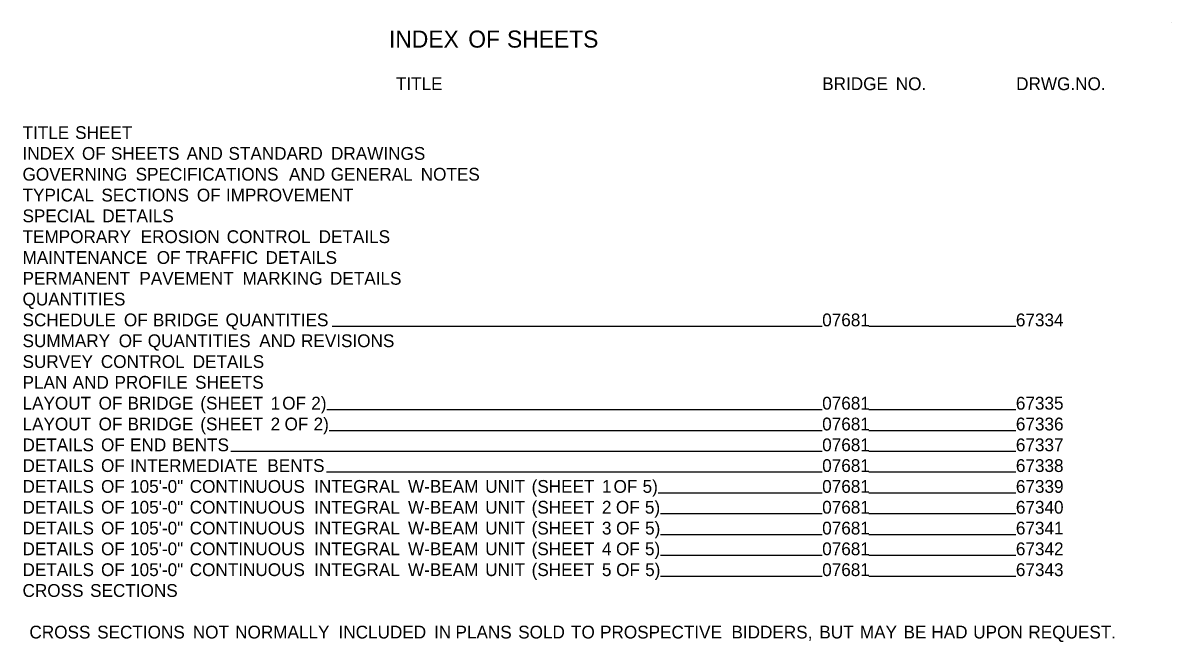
# Model space of a CAD drawing. Extents: x 1334719.7 to 1334768.4, y 402732.4 to 402752.
# Drawn here: x 1334740.16 to 1334753.59, y 402740.62 to 402747.87 of the extents above; entities that cross this region are included whole.
import ezdxf

# ---------------------------------------------------------------- set-up
doc = ezdxf.new("R2010")
doc.units = 0
doc.layers.add('Default', color=7, linetype='Continuous')

msp = doc.modelspace()

# ---------------------------------------------------------------- linework, layer by layer
at = {"layer": 'Default'}
for p, q in [((1334753.594, 402747.87), (1334753.594, 402747.87)), ((1334743.777, 402744.317), (1334749.511, 402744.317)), ((1334750.055, 402744.317), (1334751.778, 402744.317)), ((1334743.711, 402743.342), (1334749.511, 402743.342)), ((1334750.055, 402743.342), (1334751.778, 402743.342)), ((1334743.739, 402743.098), (1334749.511, 402743.098)), ((1334750.055, 402743.098), (1334751.778, 402743.098)), ((1334742.589, 402742.854), (1334749.511, 402742.854)), ((1334750.055, 402742.854), (1334751.778, 402742.854)), ((1334743.707, 402742.611), (1334749.511, 402742.611)), ((1334750.055, 402742.611), (1334751.778, 402742.611)), ((1334747.59, 402742.367), (1334749.511, 402742.367)), ((1334750.055, 402742.367), (1334751.778, 402742.367)), ((1334747.617, 402742.123), (1334749.511, 402742.123)), ((1334750.055, 402742.123), (1334751.778, 402742.123)), ((1334747.619, 402741.879), (1334749.511, 402741.879)), ((1334750.055, 402741.879), (1334751.778, 402741.879)), ((1334747.618, 402741.636), (1334749.511, 402741.636)), ((1334750.055, 402741.636), (1334751.778, 402741.636)), ((1334747.62, 402741.392), (1334749.511, 402741.392)), ((1334750.055, 402741.392), (1334751.778, 402741.392))]:
    msp.add_line(p, q, dxfattribs=at)

# ---------------------------------------------------------------- texts
for s, height, p in [('INDEX', 0.2, (1334744.44, 402747.581)), (' OF', 0.2, (1334745.294, 402747.581)), (' SHEETS', 0.2, (1334745.747, 402747.581)), ('TITLE', 0.15, (1334744.521, 402747.083)), ('BRIDGE', 0.15, (1334749.511, 402747.083)), (' NO.', 0.15, (1334750.316, 402747.083)), ('DRWG.NO.', 0.15, (1334751.781, 402747.083)), ('TITLE', 0.15, (1334740.151, 402746.511)), (' SHEET', 0.15, (1334740.711, 402746.511)), ('INDEX', 0.15, (1334740.151, 402746.267)), (' OF', 0.15, (1334740.791, 402746.267)), (' SHEETS', 0.15, (1334741.13, 402746.267)), (' AND', 0.15, (1334742.016, 402746.267)), (' STANDARD', 0.15, (1334742.506, 402746.267)), (' DRAWINGS', 0.15, (1334743.706, 402746.267)), ('GOVERNING', 0.15, (1334740.151, 402746.023)), (' SPECIFICATIONS', 0.15, (1334741.419, 402746.023)), (' AND', 0.15, (1334743.214, 402746.023)), (' GENERAL', 0.15, (1334743.703, 402746.023)), (' NOTES', 0.15, (1334744.756, 402746.023)), ('TYPICAL', 0.15, (1334740.151, 402745.779)), (' SECTIONS', 0.15, (1334741.018, 402745.779)), (' OF', 0.15, (1334742.136, 402745.779)), (' IMPROVEMENT', 0.15, (1334742.476, 402745.779)), ('SPECIAL', 0.15, (1334740.151, 402745.536)), (' DETAILS', 0.15, (1334741.029, 402745.536)), ('TEMPORARY', 0.15, (1334740.151, 402745.292)), (' EROSION', 0.15, (1334741.478, 402745.292)), (' CONTROL', 0.15, (1334742.485, 402745.292)), (' DETAILS', 0.15, (1334743.561, 402745.292)), ('MAINTENANCE', 0.15, (1334740.151, 402745.048)), (' OF', 0.15, (1334741.666, 402745.048)), (' TRAFFIC', 0.15, (1334742.006, 402745.048)), (' DETAILS', 0.15, (1334742.94, 402745.048)), ('PERMANENT', 0.15, (1334740.151, 402744.804)), (' PAVEMENT', 0.15, (1334741.463, 402744.804)), (' MARKING', 0.15, (1334742.67, 402744.804)), (' DETAILS', 0.15, (1334743.694, 402744.804)), ('QUANTITIES', 0.15, (1334740.151, 402744.561)), ('SCHEDULE', 0.15, (1334740.151, 402744.317)), (' OF', 0.15, (1334741.282, 402744.317)), (' BRIDGE', 0.15, (1334741.621, 402744.317)), (' QUANTITIES', 0.15, (1334742.472, 402744.317)), ('07681', 0.15, (1334749.511, 402744.317)), ('67334', 0.15, (1334751.778, 402744.317)), ('SUMMARY', 0.15, (1334740.151, 402744.073)), (' OF', 0.15, (1334741.221, 402744.073)), (' QUANTITIES', 0.15, (1334741.561, 402744.073)), (' AND', 0.15, (1334742.866, 402744.073)), (' REVISIONS', 0.15, (1334743.355, 402744.073)), ('SURVEY', 0.15, (1334740.151, 402743.829)), (' CONTROL', 0.15, (1334741.012, 402743.829)), (' DETAILS', 0.15, (1334742.087, 402743.829)), ('PLAN', 0.15, (1334740.151, 402743.586)), (' AND', 0.15, (1334740.682, 402743.586)), (' PROFILE', 0.15, (1334741.171, 402743.586)), (' SHEETS', 0.15, (1334742.115, 402743.586)), ('LAYOUT', 0.15, (1334740.151, 402743.342)), (' OF', 0.15, (1334740.986, 402743.342)), (' BRIDGE', 0.15, (1334741.325, 402743.342)), (' (SHEET', 0.15, (1334742.176, 402743.342)), (' 1', 0.15, (1334742.999, 402743.342)), (' OF', 0.15, (1334743.135, 402743.342)), (' 2)', 0.15, (1334743.475, 402743.342)), ('07681', 0.15, (1334749.511, 402743.342)), ('67335', 0.15, (1334751.778, 402743.342)), ('LAYOUT', 0.15, (1334740.151, 402743.098)), (' OF', 0.15, (1334740.986, 402743.098)), (' BRIDGE', 0.15, (1334741.325, 402743.098)), (' (SHEET', 0.15, (1334742.176, 402743.098)), (' 2', 0.15, (1334742.999, 402743.098)), (' OF', 0.15, (1334743.162, 402743.098)), (' 2)', 0.15, (1334743.502, 402743.098)), ('07681', 0.15, (1334749.511, 402743.098)), ('67336', 0.15, (1334751.778, 402743.098)), ('DETAILS', 0.15, (1334740.151, 402742.854)), (' OF', 0.15, (1334741.014, 402742.854)), (' END', 0.15, (1334741.354, 402742.854)), (' BENTS', 0.15, (1334741.843, 402742.854)), ('07681', 0.15, (1334749.511, 402742.854)), ('67337', 0.15, (1334751.778, 402742.854)), ('DETAILS', 0.15, (1334740.151, 402742.611)), (' OF', 0.15, (1334741.014, 402742.611)), (' INTERMEDIATE', 0.15, (1334741.354, 402742.611)), (' BENTS', 0.15, (1334742.961, 402742.611)), ('07681', 0.15, (1334749.511, 402742.611)), ('67338', 0.15, (1334751.778, 402742.611)), ('DETAILS', 0.15, (1334740.151, 402742.367)), (' OF', 0.15, (1334741.014, 402742.367)), (' 105\'-0"', 0.15, (1334741.354, 402742.367)), (' CONTINUOUS', 0.15, (1334742.052, 402742.367)), (' INTEGRAL', 0.15, (1334743.508, 402742.367)), (' W-BEAM', 0.15, (1334744.607, 402742.367)), (' UNIT', 0.15, (1334745.511, 402742.367)), (' (SHEET', 0.15, (1334746.054, 402742.367)), (' 1', 0.15, (1334746.877, 402742.367)), (' OF', 0.15, (1334747.013, 402742.367)), (' 5)', 0.15, (1334747.353, 402742.367)), ('07681', 0.15, (1334749.511, 402742.367)), ('67339', 0.15, (1334751.778, 402742.367)), ('DETAILS', 0.15, (1334740.151, 402742.123)), (' OF', 0.15, (1334741.014, 402742.123)), (' 105\'-0"', 0.15, (1334741.354, 402742.123)), (' CONTINUOUS', 0.15, (1334742.052, 402742.123)), (' INTEGRAL', 0.15, (1334743.508, 402742.123)), (' W-BEAM', 0.15, (1334744.607, 402742.123)), (' UNIT', 0.15, (1334745.511, 402742.123)), (' (SHEET', 0.15, (1334746.054, 402742.123)), (' 2', 0.15, (1334746.877, 402742.123)), (' OF', 0.15, (1334747.041, 402742.123)), (' 5)', 0.15, (1334747.38, 402742.123)), ('07681', 0.15, (1334749.511, 402742.123)), ('67340', 0.15, (1334751.778, 402742.123)), (' (SHEET', 0.15, (1334746.054, 402741.879)), (' 5)', 0.15, (1334747.382, 402741.879)), ('DETAILS', 0.15, (1334740.151, 402741.879)), (' OF', 0.15, (1334741.014, 402741.879)), (' 105\'-0"', 0.15, (1334741.354, 402741.879)), (' CONTINUOUS', 0.15, (1334742.052, 402741.879)), (' INTEGRAL', 0.15, (1334743.508, 402741.879)), (' W-BEAM', 0.15, (1334744.607, 402741.879)), (' UNIT', 0.15, (1334745.511, 402741.879)), (' 3', 0.15, (1334746.877, 402741.879)), (' OF', 0.15, (1334747.042, 402741.879)), ('07681', 0.15, (1334749.511, 402741.879)), ('67341', 0.15, (1334751.778, 402741.879)), ('DETAILS', 0.15, (1334740.151, 402741.636)), (' OF', 0.15, (1334741.014, 402741.636)), (' 105\'-0"', 0.15, (1334741.354, 402741.636)), (' CONTINUOUS', 0.15, (1334742.052, 402741.636)), (' INTEGRAL', 0.15, (1334743.508, 402741.636)), (' W-BEAM', 0.15, (1334744.607, 402741.636)), (' UNIT', 0.15, (1334745.511, 402741.636)), (' (SHEET', 0.15, (1334746.054, 402741.636)), (' 4', 0.15, (1334746.877, 402741.636)), (' OF', 0.15, (1334747.042, 402741.636)), (' 5)', 0.15, (1334747.381, 402741.636)), ('07681', 0.15, (1334749.511, 402741.636)), ('67342', 0.15, (1334751.778, 402741.636)), ('DETAILS', 0.15, (1334740.151, 402741.392)), (' OF', 0.15, (1334741.014, 402741.392)), (' 105\'-0"', 0.15, (1334741.354, 402741.392)), (' CONTINUOUS', 0.15, (1334742.052, 402741.392)), (' INTEGRAL', 0.15, (1334743.508, 402741.392)), (' W-BEAM', 0.15, (1334744.607, 402741.392)), (' UNIT', 0.15, (1334745.511, 402741.392)), (' (SHEET', 0.15, (1334746.054, 402741.392)), (' 5', 0.15, (1334746.877, 402741.392)), (' OF', 0.15, (1334747.043, 402741.392)), (' 5)', 0.15, (1334747.383, 402741.392)), ('07681', 0.15, (1334749.511, 402741.392)), ('67343', 0.15, (1334751.778, 402741.392)), ('CROSS', 0.15, (1334740.151, 402741.148)), (' SECTIONS', 0.15, (1334740.886, 402741.148)), (' CROSS', 0.15, (1334740.176, 402740.661)), (' SECTIONS', 0.15, (1334740.969, 402740.661)), (' NOT', 0.15, (1334742.088, 402740.661)), (' NORMALLY', 0.15, (1334742.584, 402740.661)), (' INCLUDED', 0.15, (1334743.794, 402740.661)), (' IN', 0.15, (1334744.912, 402740.661)), (' PLANS', 0.15, (1334745.163, 402740.661)), (' SOLD', 0.15, (1334745.897, 402740.661)), (' TO', 0.15, (1334746.515, 402740.661)), (' PROSPECTIVE', 0.15, (1334746.855, 402740.661)), (' BIDDERS,', 0.15, (1334748.393, 402740.661)), (' BUT', 0.15, (1334749.422, 402740.661)), (' MAY', 0.15, (1334749.896, 402740.661)), (' BE', 0.15, (1334750.407, 402740.661)), (' HAD', 0.15, (1334750.733, 402740.661)), (' UPON', 0.15, (1334751.223, 402740.661)), (' REQUEST.', 0.15, (1334751.869, 402740.661))]:
    msp.add_text(s, height=height, dxfattribs=at).set_placement(p)

doc.saveas('drawing.dxf')
